// Mitsubishi GX Works2 project: ENCODER_C252_A_X1_B_X2   PLC: FX3G

// task Task_01 (event TRUE, interval 0, priority 31): POU_01

PROGRAM POU_01
VAR
  ENCODER_1 : ENCODER;
  OUT_ENCODER : DINT;
  OUT1_ENCODER : INT;
END_VAR
(* structured ladder/FBD written out as ST: instructions are called as NAME(EN, inputs, outputs); _pN, _eN, _tN stand for wires *)
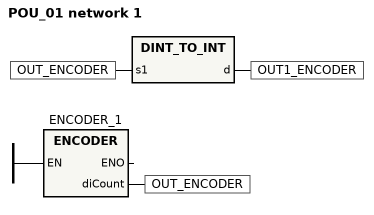
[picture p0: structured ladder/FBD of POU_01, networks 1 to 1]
(* network 1 *)
OUT1_ENCODER := DINT_TO_INT(OUT_ENCODER);
ENCODER_1(EN := TRUE, diCount => OUT_ENCODER);
END_PROGRAM

FUNCTION_BLOCK ENCODER
VAR_OUTPUT
  diCount : DINT;
END_VAR
OUT_C_32(TRUE, CC252 ,K1000 );
M0:=CS252;
diCount :=CN252;
END_FUNCTION_BLOCK
